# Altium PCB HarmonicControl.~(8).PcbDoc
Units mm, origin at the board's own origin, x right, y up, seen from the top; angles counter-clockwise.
Board outline 133.86 x 40.01 mm, 2 copper layers (Top Layer, Bottom Layer); 10 components, 14 nets, 57 pads, 0 vias.
Unrouted connection lines stored in the file: 5.
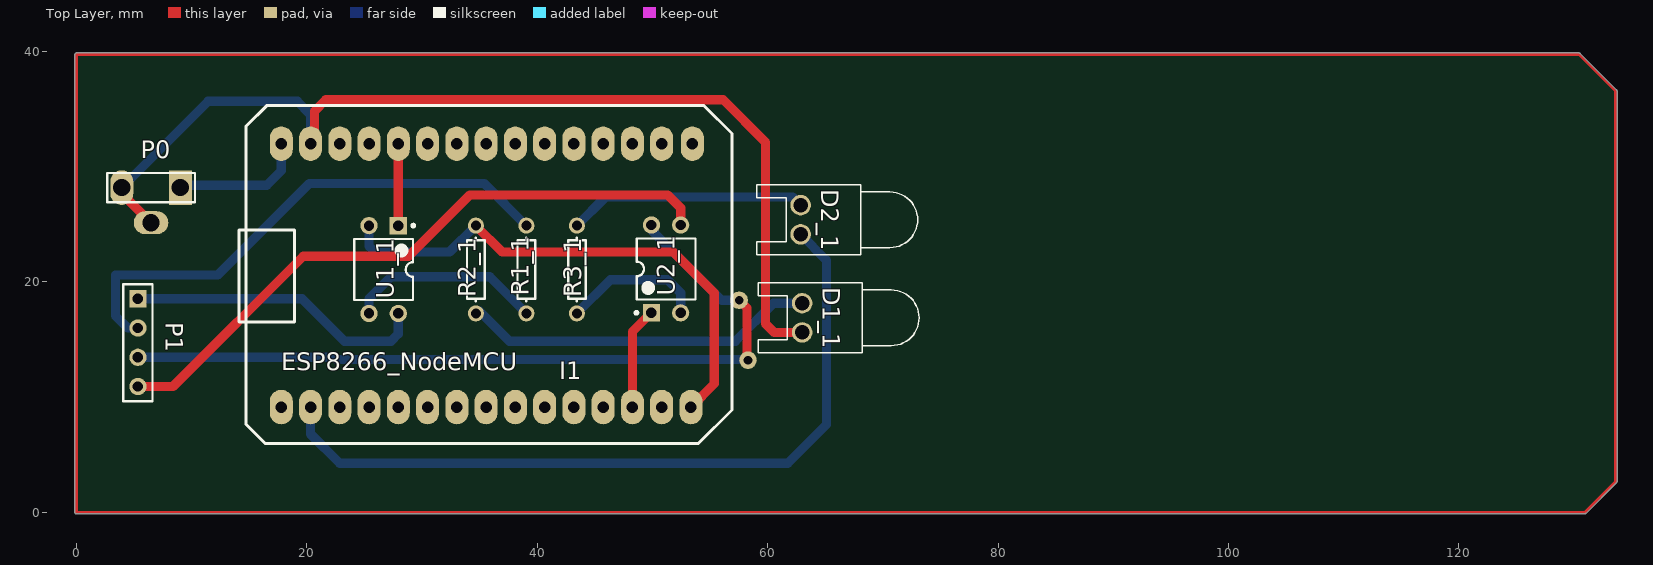
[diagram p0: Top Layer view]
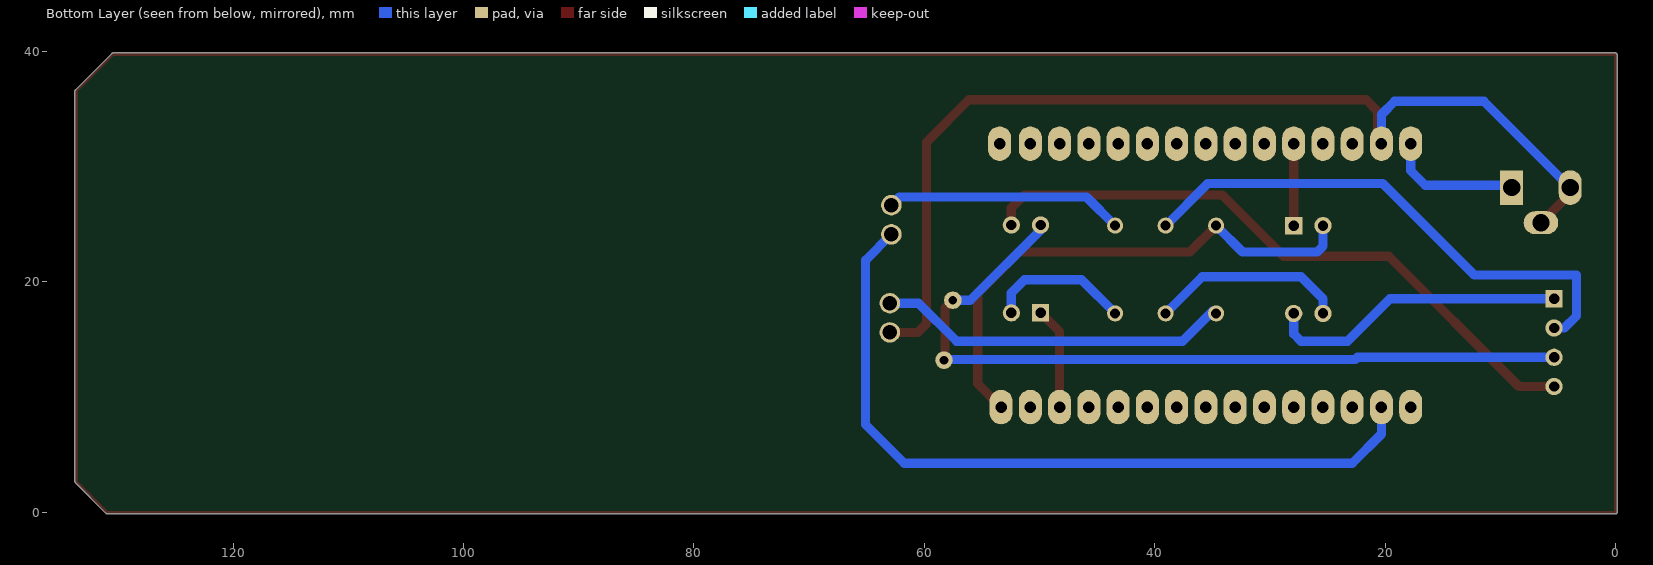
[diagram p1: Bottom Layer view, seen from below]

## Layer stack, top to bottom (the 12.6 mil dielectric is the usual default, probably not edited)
Top Solder: solder mask 0.0102, Solder Resist, Dk 3.5
Top Layer: signal copper 0.0356
Dielectric 1: dielectric 0.32, FR-4, Dk 4.8
Bottom Layer: signal copper 0.0356
Bottom Solder: solder mask 0.0102, Solder Resist, Dk 3.5

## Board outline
0.064,-0.11 cw(c0,0) -0.127,0 -0.127,39.751 cw(c0,39.751) 0,39.878 130.429,39.878 cw(c130.429,39.751) 130.52,39.841 130.519,39.841 133.694,36.666 133.694,36.667 cw(c133.604,36.576) 133.731,36.576 133.731,2.667 cw(c133.604,2.667) 133.694,2.576 133.694,2.577 131.027,-0.09 131.028,-0.09 cw(c130.937,0) 130.937,-0.127 0.127,-0.127 cw(c0.127,0)

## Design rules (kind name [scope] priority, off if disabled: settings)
Clearance [All] p1: gap=0.8 ignorepadtopadclearanceinfootprint=FALSE
PolygonConnect [All] p1: connectstyle=Relief reliefconductorwidth=0.254 reliefentries=4 polygonreliefangle="90 Angle" airgapwidth=0.254
RoutingVias [All] p1: holewidth=0.711 width=1.27 viastyle="Through Hole" minholewidth=0.711 minwidth=1.27 maxholewidth=0.711 maxwidth=1.27
SolderMaskExpansion [All] p1: expansion=0.102
Width [All] p1: maxlimit=1 minlimit=0.5 preferedwidth=0.8
30 further rules are at their usual default settings.

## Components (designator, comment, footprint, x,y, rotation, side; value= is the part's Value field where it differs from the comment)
D1_1 "LED0" LED-0 62.992,16.891 r90 top
D2_1 "LED0" LED-0 62.865,25.4 r90 top
I1 "ESP8266" ESP8266_Node_MCU_V3 17.78,32.004 r270 top
P0 "Jack3.5mm" HDR1X3 9.017,28.194 r180 top
P1 "Cable" HDR1X4 5.334,18.542 r270 top
R1_1 "Res1" AXIAL-0.3 39.056,21.082 r90 top value=1K
R2_1 "Res1" AXIAL-0.3 34.671,21.082 r270 top value=1K
R3_1 "Res1" AXIAL-0.3 43.441,21.082 r270 top value=1K
U1_1 "InputSignal" DIP-4 26.67,21.082 r270 top
U2_1 "Output_Control" DIP-4 51.181,21.132 r90 top

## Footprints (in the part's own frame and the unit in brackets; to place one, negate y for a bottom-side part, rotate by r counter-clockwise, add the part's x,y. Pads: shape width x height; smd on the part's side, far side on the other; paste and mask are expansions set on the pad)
AXIAL-0.3 [mm] "Axial Device, Thru-Hole; 2 Leads; 0.3 in Pin Spacing"
  round 1.4 hole 0.85: 1(-3.81,0) 2(3.81,0)
  silkscreen extent -2.77,-0.76 2.77,0.76
DIP-4 [mm] "DIP; 4 Leads; Row Spacing 7.62 mm; Pitch 2.54 mm"
  rect 1.5x1.5 hole 0.9: 1(-3.81,1.27)
  round 1.5 hole 0.9: 2(-3.81,-1.27) 3(3.81,-1.27) 4(3.81,1.27)
  silkscreen extent -3.93,-2.55 2.65,2.7, body extent -3.15,-2.5 3.15,2.5, height 5.6
ESP8266_Node_MCU_V3 [mm]
  oval 3x2 hole 1 paste+0 mask+0.102: 1(22.86,35.56) 2(22.86,33.02) 3(22.86,30.48) 4(22.86,27.94) 5(22.86,25.4) 6(22.86,22.86) 7(22.86,20.32) 8(22.86,17.78) 9(22.86,15.24) 10(22.86,12.7) 11(22.86,10.16) 12(22.86,7.62) 13(22.86,5.08) 14(22.86,2.54) 15(22.86,0) 16(0,0) 17(0,2.54) 18(0,5.08) 19(0,7.62) 20(0,10.16) 21(0,12.7) 22(0,15.24) 23(0,17.78) 24(0,20.32) 25(0,22.86) 26(0,25.4) 27(0,27.94) 28(0,30.48) 29(0,33.02) 30(0,35.687)
  silkscreen extent -3.3,-3.68 26.04,39.12
HDR1X3 [mm] "Connector; Header; 3 Position"
  rect 2x3 hole 1.5: 1(0,0)
  oval 3x2 hole 1.5: 2(2.54,3.05)
  oval 2x3 hole 1.5: 3(5.08,0)
  silkscreen extent -1.27,-1.27 6.35,1.27
HDR1X4 [mm] "Connector; Header; 4 Position"
  rect 1.5x1.5 hole 0.9: 1(0,0)
  round 1.5 hole 0.9: 2(2.54,0) 3(5.08,0) 4(7.62,0)
  silkscreen extent -1.27,-1.27 8.89,1.27
LED-0 [mil] "LED; 2 Leads"
  round 70 hole 50: 1(50,0) 2(-50,0)
  silkscreen extent -120,-400 120,150

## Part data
D1_1 D2_1: "Typical INFRARED GaAs LED"
I1: library part ESP8266_Node_MCU_V3
P0: library part "Header 3", "Header, 3-Pin"
P1: library part "Header 4", "Header, 4-Pin"
R1_1 R2_1 R3_1: "Resistor"
U1_1 U2_1: library part Optoisolator1, "4-Pin Phototransistor Optocoupler"

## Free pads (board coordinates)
  round 1.524 hole 0.762: 5(58.293,13.208) 6(57.531,18.415)

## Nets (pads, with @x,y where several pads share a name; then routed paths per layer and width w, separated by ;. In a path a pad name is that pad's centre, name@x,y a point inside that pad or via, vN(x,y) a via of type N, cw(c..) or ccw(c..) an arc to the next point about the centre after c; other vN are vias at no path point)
GND: D1_1.2 I1.17 P0.2 P0.3 | length 89.9
  Top Layer w0.8: P0.3 3.937,27.684 P0.2 ; I1.17 20.66,32.344 20.66,34.824 21.65,35.814 56.134,35.814 59.817,32.131 59.817,16.383 60.579,15.621 D1_1.2
  Bottom Layer w0.8: P0.3 11.43,35.687 19.177,35.687 20.32,34.544 I1.17
NetD1_1_1: D1_1.1 R2_1.2 | length 30.5
  Bottom Layer w0.8: R2_1.2@34.925,17.526 37.592,14.859 57.201,14.859 60.503,18.161 D1_1.1
NetD2_1_1: D2_1.1 R3_1.1 | length 20.7
  Bottom Layer w0.8: R3_1.1 45.93,27.381 62.154,27.381 D2_1.1
NetD2_1_2: D2_1.2 I1.14 | length 67
  Bottom Layer w0.8: I1.14 20.32,6.807 22.86,4.267 61.747,4.267 65.1,7.62 65.1,21.895 D2_1.2
NetI1_1: I1.1 R2_1.1 U1_1.3 | length 46.1
  Top Layer w0.8: R2_1.1 36.957,22.606 51.816,22.606 55.372,19.05 55.372,11.176 I1.1
  Bottom Layer w0.8: 25.4,24.892 25.4,23.114 25.908,22.606 32.385,22.606 R2_1.1
NetI1_3: I1.3 U2_1.1 | length 8.9
  Top Layer w0.8: I1.3 48.26,15.671 U2_1.1
NetI1_16: I1.16 P0.1 | length 11.8
  Bottom Layer w0.8: P0.1 9.017,28.397 16.51,28.397 17.78,29.667 I1.16
NetI1_20: I1.20 U1_1.4 | length 7.1
  Top Layer w0.8: 27.94,24.892 I1.20
NetP1_1: P1.1 U1_1.1 | length 26.2
  Bottom Layer w0.8: P1.1 19.583,18.542 23.266,14.859 27.305,14.859 27.94,15.494 27.94,17.272
NetP1_2: P1.2 R1_1.1 | length 46.4
  Bottom Layer w0.8: P1.2 4.445,16.002 3.378,17.069 3.378,20.599 12.268,20.599 20.218,28.55 35.398,28.55 39.056,24.892
NetP1_3: P1.3 pad.5 pad.6 U2_1.4 | length 68.8
  Top Layer w0.8: pad.6 58.217,17.729 58.217,13.284 pad.5
  Bottom Layer w0.8: P1.3 22.401,13.462 22.604,13.259 pad.5@57.988,13.259 ; U2_1.4 49.911,24.511 56.007,18.415 pad.6
NetP1_4: P1.4 U2_1.3 | length 56
  Top Layer w0.8: P1.4 8.382,10.922 19.685,22.225 28.829,22.225 34.163,27.559 51.308,27.559 52.451,26.416 U2_1.3
NetR1_1_2: R1_1.2 U1_1.2
NetR3_1_2: R3_1.2 U2_1.2 | length 11.8
  Bottom Layer w0.8: R3_1.2 46.362,20.193 51.308,20.193 52.451,19.05 U2_1.2@52.451,17.912
pads on no net: I1.2 I1.4 I1.5 I1.6 I1.7 I1.8 I1.9 I1.10 I1.11 I1.12 I1.13 I1.15 I1.18 I1.19 I1.21 I1.22 I1.23 I1.24 I1.25 I1.26 I1.27 I1.28 I1.29 I1.30
copper on no net: | length 360.2
  Top Layer w0.254: 0,0 0,39.751 130.429,39.751 133.604,36.576 133.604,2.667 130.937,0 0.127,0
  Bottom Layer w0.8: 25.4,17.272 25.4,18.542 27.305,20.447 35.881,20.447 39.056,17.272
